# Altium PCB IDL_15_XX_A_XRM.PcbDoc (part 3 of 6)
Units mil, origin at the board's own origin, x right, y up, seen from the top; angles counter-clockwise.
Board outline 6653.34 x 6653.34 mil, 6 copper layers (Top Layer - SIG1, Layer 2 - GND1, Layer 3 - PWR, Layer 4 - PWR, Layer 5 - GND2, Bottom Layer - SIG4), stack 59.843 mil thick; 613 components, 324 nets, 1673 pads, 2316 vias.
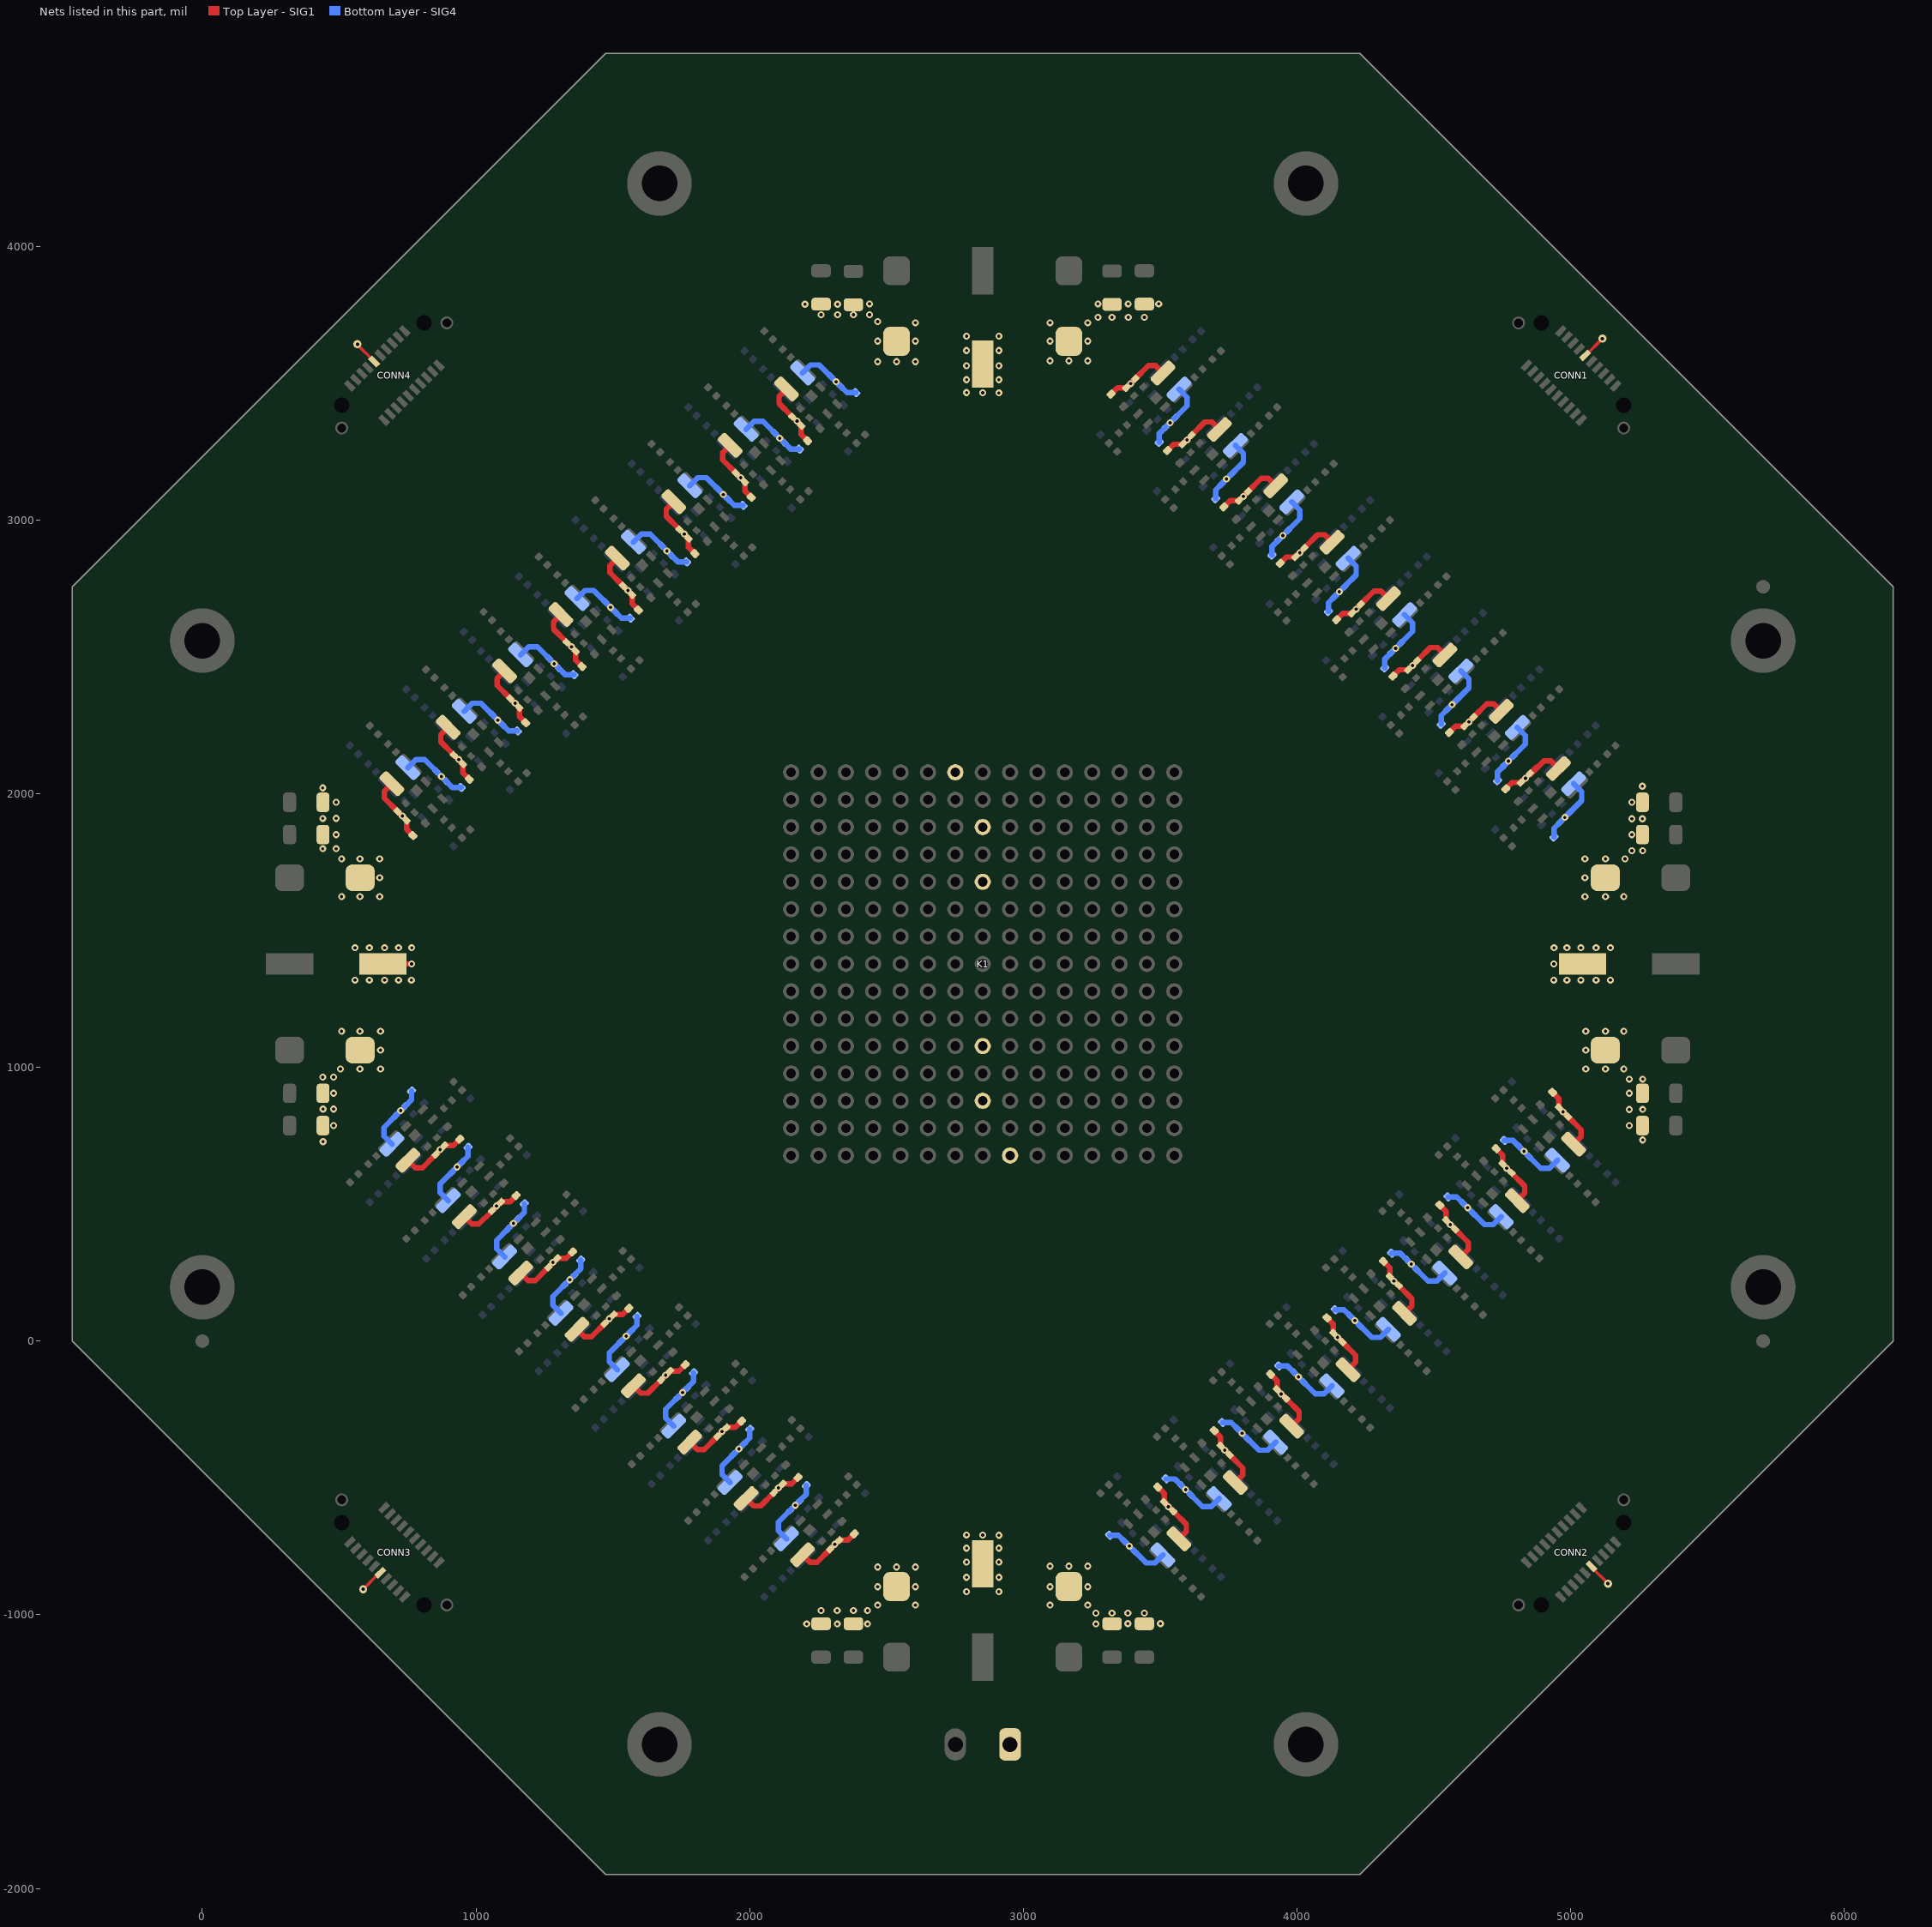
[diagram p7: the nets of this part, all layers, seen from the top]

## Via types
v1: diameter 25.59, hole 11.81, Layer 5 - GND2 to Bottom Layer - SIG4, tented both sides, 1069 vias
v2: diameter 25.59, hole 11.81, Top Layer - SIG1 to Layer 2 - GND1, tented both sides, 851 vias
v3: diameter 25.59, hole 11.81, Top Layer - SIG1 to Bottom Layer - SIG4, tented both sides, 384 vias
v4: diameter 29.53, hole 11.81, Top Layer - SIG1 to Bottom Layer - SIG4, tented both sides, 8 vias
v5: diameter 29.53, hole 11.81, Top Layer - SIG1 to Layer 2 - GND1, tented both sides, 4 vias

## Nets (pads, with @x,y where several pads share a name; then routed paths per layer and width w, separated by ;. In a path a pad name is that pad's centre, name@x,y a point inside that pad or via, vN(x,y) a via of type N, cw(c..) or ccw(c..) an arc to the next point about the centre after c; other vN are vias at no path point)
3V3: A1_C1.1 A1_C2.1 A1_C3.1 A1_L1.2 A2_C1.1 A2_C2.1 A2_C3.1 A2_L1.2 A3_C1.1 A3_C2.1 A3_C3.1 A3_L1.2 A4_C1.1 A4_C2.1 A4_C3.1 A4_L1.2 A5_C1.1 A5_C2.1 A5_C3.1 A5_L1.2 A6_C1.1 A6_C2.1 A6_C3.1 A6_L1.2 A7_C1.1 A7_C2.1 A7_C3.1 A7_L1.2 A8_C1.1 A8_C2.1 A8_C3.1 A8_L1.2 A9_C1.1 A9_C2.1 A9_C3.1 A9_L1.2 A10_C1.1 A10_C2.1 A10_C3.1 A10_L1.2 A11_C1.1 A11_C2.1 A11_C3.1 A11_L1.2 A12_C1.1 A12_C2.1 A12_C3.1 A12_L1.2 A13_C1.1 A13_C2.1 A13_C3.1 A13_L1.2 A14_C1.1 A14_C2.1 A14_C3.1 A14_L1.2 A15_C1.1 A15_C2.1 A15_C3.1 A15_L1.2 A16_C1.1 A16_C2.1 A16_C3.1 A16_L1.2 A17_C1.1 A17_C2.1 A17_C3.1 A17_L1.2 A18_C1.1 A18_C2.1 A18_C3.1 A18_L1.2 A19_C1.1 A19_C2.1 A19_C3.1 A19_L1.2 A20_C1.1 A20_C2.1 A20_C3.1 A20_L1.2 A21_C1.1 A21_C2.1 A21_C3.1 A21_L1.2 A22_C1.1 A22_C2.1 A22_C3.1 A22_L1.2 A23_C1.1 A23_C2.1 A23_C3.1 A23_L1.2 A24_C1.1 A24_C2.1 A24_C3.1 A24_L1.2 A25_C1.1 A25_C2.1 A25_C3.1 A25_L1.2 A26_C1.1 A26_C2.1 A26_C3.1 A26_L1.2 A27_C1.1 A27_C2.1 A27_C3.1 A27_L1.2 A28_C1.1 A28_C2.1 A28_C3.1 A28_L1.2 A29_C1.1 A29_C2.1 A29_C3.1 A29_L1.2 A30_C1.1 A30_C2.1 A30_C3.1 A30_L1.2 A31_C1.1 A31_C2.1 A31_C3.1 A31_L1.2 A32_C1.1 A32_C2.1 A32_C3.1 A32_L1.2 A33_C1.1 A33_C2.1 A33_C3.1 A33_L1.2 A34_C1.1 A34_C2.1 A34_C3.1 A34_L1.2 A35_C1.1 A35_C2.1 A35_C3.1 A35_L1.2 A36_C1.1 A36_C2.1 A36_C3.1 A36_L1.2 A37_C1.1 A37_C2.1 A37_C3.1 A37_L1.2 A38_C1.1 A38_C2.1 A38_C3.1 A38_L1.2 A39_C1.1 A39_C2.1 A39_C3.1 A39_L1.2 A40_C1.1 A40_C2.1 A40_C3.1 A40_L1.2 A41_C1.1 A41_C2.1 A41_C3.1 A41_L1.2 A42_C1.1 A42_C2.1 A42_C3.1 A42_L1.2 A43_C1.1 A43_C2.1 A43_C3.1 A43_L1.2 A44_C1.1 A44_C2.1 A44_C3.1 A44_L1.2 A45_C1.1 A45_C2.1 A45_C3.1 A45_L1.2 A46_C1.1 A46_C2.1 A46_C3.1 A46_L1.2 A47_C1.1 A47_C2.1 A47_C3.1 A47_L1.2 A48_C1.1 A48_C2.1 A48_C3.1 A48_L1.2 A49_C1.1 A49_C2.1 A49_C3.1 A49_L1.2 A50_C1.1 A50_C2.1 A50_C3.1 A50_L1.2 A51_C1.1 A51_C2.1 A51_C3.1 A51_L1.2 A52_C1.1 A52_C2.1 A52_C3.1 A52_L1.2 A53_C1.1 A53_C2.1 A53_C3.1 A53_L1.2 A54_C1.1 A54_C2.1 A54_C3.1 A54_L1.2 A55_C1.1 A55_C2.1 A55_C3.1 A55_L1.2 A56_C1.1 A56_C2.1 A56_C3.1 A56_L1.2 A57_C1.1 A57_C2.1 A57_C3.1 A57_L1.2 A58_C1.1 A58_C2.1 A58_C3.1 A58_L1.2 A59_C1.1 A59_C2.1 A59_C3.1 A59_L1.2 A60_C1.1 A60_C2.1 A60_C3.1 A60_L1.2 A61_C1.1 A61_C2.1 A61_C3.1 A61_L1.2 A62_C1.1 A62_C2.1 A62_C3.1 A62_L1.2 A63_C1.1 A63_C2.1 A63_C3.1 A63_L1.2 A64_C1.1 A64_C2.1 A64_C3.1 A64_L1.2 C4.1 C5.1 C6.1 C7.1 C8.1 C9.1 C10.1 C11.1 C12.1 C14.1 C15.1 C16.1 C17.1 C18.1 C19.1 C20.1 C21.1 C22.1 C23.1 C24.1 C25.1 C26.1 C27.1 C28.1 C29.1 C30.1 C31.1 C32.1 K2.1 | length 17087.9
  Top Layer - SIG1 w20: C32.1@659.5,1377.95 v3(764.82,1377.95) ; 691.01,1957.49 A5_C1.1@713.06,1935.44 ; A5_L1.2@692.59,2036.63 665.16,2009.2 665.16,1983.34 A5_C1.1@713.06,1935.44 ; A4_L1.2@751.12,660.84 778.55,633.41 804.41,633.41 A4_C1.1@852.31,681.3 ; A5_C3.1@769.41,1847.03 746.46,1869.98 A5_C2.1@746.46,1902.03 A5_C1.1@713.06,1935.44 ; 830.26,659.26 A4_C1.1@852.31,681.3 ; 897.02,2163.5 A6_C1.1@919.06,2141.45 ; A6_L1.2@898.6,2242.64 871.17,2215.21 871.17,2189.34 A6_C1.1@919.06,2141.45 ; A4_C3.1@940.72,737.66 917.77,714.71 A4_C2.1@885.72,714.71 A4_C1.1@852.31,681.3 ; A3_L1.2@957.12,454.84 984.56,427.4 1010.42,427.4 A3_C1.1@1058.32,475.3 ; A6_C3.1@975.42,2053.04 952.47,2075.99 A6_C2.1@952.47,2108.04 A6_C1.1@919.06,2141.45 ; 1036.27,453.25 A3_C1.1@1058.32,475.3 ; 1103.02,2369.5 A7_C1.1@1125.07,2347.45 ; A7_L1.2@1104.61,2448.65 1077.17,2421.21 1077.17,2395.35 A7_C1.1@1125.07,2347.45 ; A3_C3.1@1146.72,531.65 1123.77,508.7 A3_C2.1@1091.73,508.7 A3_C1.1@1058.32,475.3 ; A2_L1.2@1163.13,248.83 1190.57,221.39 1216.43,221.39 A2_C1.1@1264.33,269.29 ; A7_C3.1@1181.43,2259.05 1158.48,2282 A7_C2.1@1158.48,2314.05 A7_C1.1@1125.07,2347.45 ; 1242.28,247.24 A2_C2.1@1297.73,302.7 1329.78,302.7 A2_C3.1@1352.73,325.65 ; 1309.03,2575.51 A8_C1.1@1331.08,2553.46 ; A8_L1.2@1310.62,2654.66 1283.18,2627.22 1283.18,2601.36 A8_C1.1@1331.08,2553.46 ; A1_L1.2@1368.78,43.18 1396.22,15.74 1422.08,15.74 A1_C1.1@1469.98,63.64 ; A8_C3.1@1387.44,2465.06 1364.49,2488.01 A8_C2.1@1364.49,2520.06 A8_C1.1@1331.08,2553.46 ; 1447.93,41.59 A1_C2.1@1503.38,97.05 1535.43,97.04 A1_C3.1@1558.38,120 ; 1515.07,2781.55 A25_C1.1@1537.12,2759.5 ; A25_L1.2@1516.66,2860.7 1489.22,2833.26 1489.22,2807.4 A25_C1.1@1537.12,2759.5 ; A64_L1.2@1574.82,-162.86 1602.26,-190.3 1628.12,-190.3 A64_C1.1@1676.02,-142.4 ; A25_C3.1@1593.48,2671.1 1570.53,2694.05 A25_C2.1@1570.53,2726.1 A25_C1.1@1537.12,2759.5 ; 1653.97,-164.45 A64_C2.1@1709.42,-109 1741.47,-109 A64_C3.1@1764.42,-86.05 ; 1721.08,2987.56 A26_C1.1@1743.13,2965.51 ; A26_L1.2@1722.67,3066.7 1695.23,3039.27 1695.23,3013.41 A26_C1.1@1743.13,2965.51 ; A63_L1.2@1780.86,-368.9 1808.3,-396.34 1834.16,-396.34 A63_C1.1@1882.06,-348.44 ; A26_C3.1@1799.48,2877.11 1776.53,2900.06 A26_C2.1@1776.53,2932.1 A26_C1.1@1743.13,2965.51 ; 1860.01,-370.49 A63_C2.1@1915.47,-315.04 1947.51,-315.04 A63_C3.1@1970.46,-292.09 ; 1927.09,3193.57 A27_C1.1@1949.13,3171.52 ; A27_L1.2@1928.67,3272.71 1901.24,3245.28 1901.24,3219.41 A27_C1.1@1949.13,3171.52 ; A62_L1.2@1986.87,-574.91 2014.31,-602.35 2040.17,-602.35 A62_C1.1@2088.07,-554.45 ; A27_C3.1@2005.49,3083.11 1982.54,3106.06 A27_C2.1@1982.54,3138.11 A27_C1.1@1949.13,3171.52 ; 2066.02,-576.5 A62_C2.1@2121.47,-521.04 2153.52,-521.04 A62_C3.1@2176.47,-498.09 ; 2133.09,3399.57 A28_C1.1@2155.14,3377.53 ; A28_L1.2@2134.68,3478.72 2107.25,3451.28 2107.25,3425.42 A28_C1.1@2155.14,3377.53 ; A61_L1.2@2192.88,-780.92 2220.31,-808.35 2246.18,-808.35 A61_C1.1@2294.07,-760.46 ; A28_C3.1@2211.5,3289.12 2188.55,3312.07 A28_C2.1@2188.55,3344.12 A28_C1.1@2155.14,3377.53 ; 2272.03,-782.51 A61_C2.1@2327.48,-727.05 2359.53,-727.05 A61_C3.1@2382.48,-704.1 ; A29_C3.1@3320.52,3459.77 3343.47,3482.72 A29_C2.1@3375.51,3482.72 A29_C1.1@3408.92,3516.13 ; 3430.97,3538.18 A29_C1.1@3408.92,3516.13 ; A60_C3.1@3491.33,-533.25 3514.28,-556.2 A60_C2.1@3514.28,-588.25 3569.74,-643.7 ; A29_L1.2@3510.12,3536.59 3482.68,3564.03 3456.82,3564.03 A29_C1.1@3408.92,3516.13 ; A30_C3.1@3526.52,3253.77 3549.47,3276.72 A30_C2.1@3581.52,3276.72 A30_C1.1@3614.93,3310.12 ; A60_C1.1@3547.69,-621.65 3595.59,-669.55 3595.59,-695.41 A60_L1.2@3568.15,-722.85 ; 3636.98,3332.17 A30_C1.1@3614.93,3310.12 ; A59_C3.1@3697.34,-327.24 3720.29,-350.19 A59_C2.1@3720.29,-382.24 3775.75,-437.69 ; A30_L1.2@3716.12,3330.59 3688.69,3358.02 3662.82,3358.02 A30_C1.1@3614.93,3310.12 ; A31_C3.1@3732.53,3047.76 3755.48,3070.71 A31_C2.1@3787.53,3070.71 A31_C1.1@3820.94,3104.12 ; A59_C1.1@3753.7,-415.65 3801.59,-463.54 3801.59,-489.4 A59_L1.2@3774.16,-516.84 ; 3842.98,3126.17 A31_C1.1@3820.94,3104.12 ; A58_C3.1@3903.35,-121.23 3926.3,-144.18 A58_C2.1@3926.3,-176.23 3981.75,-231.69 ; A31_L1.2@3922.13,3124.58 3894.69,3152.01 3868.83,3152.01 A31_C1.1@3820.94,3104.12 ; A32_C3.1@3938.54,2841.75 3961.49,2864.7 A32_C2.1@3993.54,2864.7 A32_C1.1@4026.94,2898.11 ; A58_C1.1@3959.71,-209.64 4007.6,-257.53 4007.6,-283.4 A58_L1.2@3980.17,-310.83 ; 4048.99,2920.16 A32_C1.1@4026.94,2898.11 ; A57_C3.1@4109.39,84.81 4132.34,61.86 A57_C2.1@4132.34,29.81 A57_C1.1@4165.75,-3.6 ; A32_L1.2@4128.14,2918.57 4100.7,2946.01 4074.84,2946.01 A32_C1.1@4026.94,2898.11 ; A41_C3.1@4144.58,2635.71 4167.53,2658.66 A41_C2.1@4199.58,2658.66 A41_C1.1@4232.98,2692.07 ; A57_L1.2@4186.21,-104.79 4213.64,-77.36 4213.64,-51.49 A57_C1.1@4165.75,-3.6 ; 4187.8,-25.65 A57_C1.1@4165.75,-3.6 ; 4255.03,2714.12 A41_C1.1@4232.98,2692.07 ; A48_C3.1@4315.43,290.85 4338.38,267.9 A48_C2.1@4338.38,235.85 A48_C1.1@4371.79,202.44 ; A41_L1.2@4334.18,2712.53 4306.74,2739.96 4280.88,2739.96 A41_C1.1@4232.98,2692.07 ; A42_C3.1@4350.59,2429.7 4373.54,2452.65 A42_C2.1@4405.59,2452.65 A42_C1.1@4438.99,2486.06 ; A48_L1.2@4392.25,101.25 4419.68,128.68 4419.68,154.55 A48_C1.1@4371.79,202.44 ; 4393.84,180.4 A48_C1.1@4371.79,202.44 ; 4461.04,2508.11 A42_C1.1@4438.99,2486.06 ; A47_C3.1@4521.44,496.86 4544.39,473.91 A47_C2.1@4544.39,441.86 4599.84,386.4 ; A42_L1.2@4540.19,2506.52 4512.75,2533.96 4486.89,2533.96 A42_C1.1@4438.99,2486.06 ; A43_C3.1@4556.59,2223.7 4579.54,2246.65 A43_C2.1@4611.59,2246.65 A43_C1.1@4645,2280.05 ; A47_C1.1@4577.8,408.45 4625.69,360.56 4625.69,334.69 A47_L1.2@4598.26,307.26 ; 4667.05,2302.1 A43_C1.1@4645,2280.05 ; A46_C3.1@4727.45,702.86 4750.4,679.91 A46_C2.1@4750.4,647.87 A46_C1.1@4783.8,614.46 ; A43_L1.2@4746.19,2300.51 4718.76,2327.95 4692.9,2327.95 A43_C1.1@4645,2280.05 ; A45_C3.1@4762.6,2017.69 4785.55,2040.64 A45_C2.1@4817.6,2040.64 A45_C1.1@4851.01,2074.05 4873.06,2096.09 ; A46_L1.2@4804.26,513.26 4831.7,540.7 4831.7,566.56 A46_C1.1@4783.8,614.46 ; 4805.85,592.41 A46_C1.1@4783.8,614.46 ; A45_C1.1@4853.79,2071.26 4901.69,2119.16 4927.55,2119.16 A45_L1.2@4954.99,2091.72 ; A44_C3.1@4933.45,908.87 4956.4,885.92 A44_C2.1@4956.4,853.87 A44_C1.1@4989.81,820.47 ; A44_L1.2@5010.27,719.27 5037.71,746.71 5037.71,772.57 A44_C1.1@4989.81,820.47 ; 5011.86,798.42 A44_C1.1@4989.81,820.47
  Bottom Layer - SIG4 w20: A13_L1.2@693.04,718.92 663.23,748.73 663.23,780.36 A13_C1.1@705.46,822.59 v3(724.95,842.07) A13_C2.1@741.65,858.78 764.62,881.74 A13_C3.1@764.62,913.76 ; A12_L1.2@750.67,2094.71 780.48,2124.52 812.11,2124.52 A12_C1.1@854.34,2082.29 v3(873.83,2062.8) A12_C2.1@890.53,2046.1 913.5,2023.13 A12_C3.1@945.51,2023.13 ; A14_L1.2@899.05,512.91 869.24,542.72 869.24,574.35 A14_C1.1@911.47,616.58 v3(930.96,636.07) A14_C2.1@947.66,652.77 970.63,675.74 A14_C3.1@970.63,707.75 ; A11_L1.2@956.67,2300.71 986.49,2330.53 1018.11,2330.53 A11_C1.1@1060.35,2288.3 v3(1079.83,2268.81) A11_C2.1@1096.54,2252.11 1119.5,2229.14 A11_C3.1@1151.52,2229.14 ; 1103.47,396.57 A15_C1.1@1117.48,410.57 ; A15_L1.2@1105.06,306.9 1075.24,336.72 1075.24,368.34 A15_C1.1@1117.48,410.57 ; A10_L1.2@1162.68,2506.72 1192.5,2536.54 1224.12,2536.54 A10_C1.1@1266.35,2494.3 v3(1285.84,2474.82) A10_C2.1@1302.54,2458.11 1325.51,2435.15 A10_C3.1@1357.53,2435.15 ; A15_C3.1@1176.63,501.74 1176.63,469.73 A15_C2.1@1153.67,446.76 v3(1136.96,430.06) A15_C1.1@1117.48,410.57 ; A16_L1.2@1310.71,101.25 1280.9,131.06 1280.9,162.69 A16_C1.1@1323.13,204.92 v3(1342.61,224.41) A16_C2.1@1359.32,241.11 1382.28,264.08 A16_C3.1@1382.28,296.09 ; A9_L1.2@1368.69,2712.73 1398.5,2742.54 1430.13,2742.54 A9_C1.1@1472.36,2700.31 v3(1491.85,2680.83) A9_C2.1@1508.55,2664.12 1531.52,2641.15 A9_C3.1@1563.53,2641.15 ; 1515.16,-15.12 v3(1548.65,18.37) A49_C2.1@1565.36,35.07 1588.32,58.04 A49_C3.1@1588.33,90.05 ; A49_L1.2@1516.75,-104.79 1486.94,-74.98 1486.94,-43.35 A49_C1.1@1529.17,-1.12 ; A24_L1.2@1574.73,2918.77 1604.55,2948.58 1636.17,2948.58 A24_C1.1@1678.4,2906.35 v3(1697.89,2886.87) A24_C2.1@1714.59,2870.16 1737.56,2847.2 A24_C3.1@1769.57,2847.2 ; 1721.21,-221.16 A50_C1.1@1735.21,-207.16 ; A50_L1.2@1722.79,-310.83 1692.98,-281.02 1692.98,-249.39 A50_C1.1@1735.21,-207.16 ; A23_L1.2@1780.74,3124.78 1810.55,3154.59 1842.18,3154.59 A23_C1.1@1884.41,3112.36 v3(1903.9,3092.87) A23_C2.1@1920.6,3076.17 1943.57,3053.2 A23_C3.1@1975.58,3053.2 ; A50_C3.1@1794.37,-115.99 1794.37,-148 A50_C2.1@1771.4,-170.97 v3(1754.7,-187.67) A50_C1.1@1735.21,-207.16 ; 1927.21,-427.17 A51_C1.1@1941.22,-413.17 ; A51_L1.2@1928.8,-516.84 1898.98,-487.03 1898.98,-455.4 A51_C1.1@1941.22,-413.17 ; A22_L1.2@1986.75,3330.78 2016.56,3360.6 2048.19,3360.6 A22_C1.1@2090.42,3318.37 v3(2109.9,3298.88) A22_C2.1@2126.61,3282.18 2149.57,3259.21 A22_C3.1@2181.59,3259.21 ; A51_C3.1@2000.37,-322 2000.37,-354.01 A51_C2.1@1977.41,-376.98 v3(1960.7,-393.68) A51_C1.1@1941.22,-413.17 ; 2133.22,-633.18 A52_C1.1@2147.22,-619.18 ; A52_L1.2@2134.81,-722.85 2104.99,-693.03 2104.99,-661.41 A52_C1.1@2147.22,-619.18 ; A21_L1.2@2192.75,3536.79 2222.57,3566.61 2254.19,3566.61 A21_C1.1@2296.42,3524.38 v3(2315.91,3504.89) A21_C2.1@2332.62,3488.19 2355.58,3465.22 A21_C3.1@2387.6,3465.22 ; A52_C3.1@2206.38,-528 2206.38,-560.02 A52_C2.1@2183.41,-582.99 v3(2166.71,-599.69) A52_C1.1@2147.22,-619.18 ; A53_C3.1@3315.24,-709.35 3347.25,-709.35 A53_C2.1@3370.22,-732.31 v3(3386.92,-749.02) A53_C1.1@3406.41,-768.5 3448.64,-810.73 3480.27,-810.73 A53_L1.2@3510.08,-780.92 ; A20_C3.1@3496.61,3283.68 3496.61,3315.69 A20_C2.1@3519.58,3338.66 v3(3536.28,3355.36) A20_C1.1@3555.77,3374.85 3598,3417.08 3598,3448.71 A20_L1.2@3568.19,3478.52 ; A54_C3.1@3521.24,-503.34 3553.26,-503.34 A54_C2.1@3576.23,-526.3 v3(3592.93,-543.01) A54_C1.1@3612.42,-562.5 3654.65,-604.73 3686.27,-604.73 A54_L1.2@3716.09,-574.91 ; A19_C3.1@3702.62,3077.67 3702.62,3109.68 A19_C2.1@3725.59,3132.65 v3(3742.29,3149.35) A19_C1.1@3761.78,3168.84 ; A55_C3.1@3727.25,-297.33 3759.27,-297.33 A55_C2.1@3782.23,-320.3 v3(3798.94,-337) A55_C1.1@3818.42,-356.49 3860.66,-398.72 3892.28,-398.72 A55_L1.2@3922.1,-368.9 ; A19_L1.2@3774.19,3272.51 3804.01,3242.7 3804.01,3211.07 A19_C1.1@3761.78,3168.84 ; 3775.78,3182.85 A19_C1.1@3761.78,3168.84 ; A18_C3.1@3908.63,2871.66 3908.63,2903.68 A18_C2.1@3931.6,2926.64 v3(3948.3,2943.35) A18_C1.1@3967.79,2962.83 4010.02,3005.07 4010.02,3036.69 A18_L1.2@3980.2,3066.51 ; A56_C3.1@3933.29,-91.29 3965.31,-91.29 A56_C2.1@3988.27,-114.26 v3(4004.98,-130.96) A56_C1.1@4024.46,-150.45 ; 4038.47,-164.45 A56_C1.1@4024.46,-150.45 ; A17_C3.1@4114.64,2665.65 4114.64,2697.67 A17_C2.1@4137.6,2720.64 v3(4154.31,2737.34) A17_C1.1@4173.79,2756.83 4216.02,2799.06 4216.02,2830.68 A17_L1.2@4186.21,2860.5 ; A56_L1.2@4128.14,-162.86 4098.32,-192.68 4066.7,-192.68 A56_C1.1@4024.46,-150.45 ; A33_C3.1@4139.33,114.75 4171.35,114.75 A33_C1.1@4230.51,55.59 4272.74,13.36 4304.36,13.36 A33_L1.2@4334.18,43.18 ; A40_C3.1@4320.68,2459.61 4320.68,2491.63 A40_C2.1@4343.64,2514.6 4422.07,2593.02 4422.07,2624.64 A40_L1.2@4392.25,2654.46 ; A34_C3.1@4345.34,320.76 4377.36,320.76 A34_C2.1@4400.32,297.79 A34_C1.1@4436.51,261.6 4478.74,219.37 4510.37,219.37 A34_L1.2@4540.18,249.19 ; A39_C3.1@4526.68,2253.61 4526.68,2285.62 A39_C1.1@4585.84,2344.78 ; A35_C3.1@4551.35,526.77 4583.36,526.77 A35_C1.1@4642.52,467.61 4684.75,425.38 4716.38,425.38 A35_L1.2@4746.19,455.19 ; A39_L1.2@4598.26,2448.45 4628.07,2418.63 4628.07,2387.01 A39_C1.1@4585.84,2344.78 ; 4599.84,2358.78 A39_C1.1@4585.84,2344.78 ; A38_C3.1@4732.69,2047.6 4732.69,2079.61 A38_C1.1@4791.85,2138.77 4834.08,2181 4834.08,2212.63 A38_L1.2@4804.27,2242.44 ; A36_C3.1@4757.36,732.77 4789.37,732.77 A36_C1.1@4848.53,673.62 ; 4862.53,659.61 A36_C1.1@4848.53,673.62 ; A37_C3.1@4938.7,1841.59 4938.7,1873.61 5011.86,1946.77 ; A36_L1.2@4952.2,661.2 4922.38,631.39 4890.76,631.39 A36_C1.1@4848.53,673.62 ; A37_C1.1@4997.86,1932.76 5040.09,1974.99 5040.09,2006.62 A37_L1.2@5010.27,2036.44
  other v3: 2208.39,-1033.46 2319.94,-1033.46 2430.48,-1033.46 3264.82,-1033.46 3381.93,-1032.48 3500.53,-1032.48 3264.82,-994.09 3323.87,-994.09 3381.93,-994.09 3442.24,-994.09 2260.88,-984.25 2319.61,-984.25 2378.99,-984.25 2430.48,-984.25 2467.57,-964.57 2605.37,-964.57 3097.5,-964.57 3235.29,-964.57 2792.38,-915.35 2910.49,-915.35 2467.57,-897.7 2605.37,-897.7 3097.5,-897.7 3235.29,-897.7 2792.38,-863.24 2910.49,-863.24 2467.57,-825.32 2536.47,-825.32 2605.37,-825.32 3097.5,-822.18 3166.39,-822.18 3235.29,-822.18 2792.38,-807.09 2910.49,-807.09 2792.38,-756.48 2910.49,-756.48 2310.78,-742.36 2910.49,-709.35 2792.38,-708.26 2851.43,-708.66 3529.6,-604.95 2104.77,-536.36 3735.6,-398.94 1898.76,-330.35 3941.61,-192.93 1692.72,-124.31 4147.65,13.11 4211.02,75.08 1486.68,81.73 4353.69,219.15 4417.03,281.09 1281.03,287.38 4559.7,425.15 4623.03,487.1 1075.02,493.39 4765.71,631.16 4829.04,693.1 869.01,699.4 441,728.86 5262.85,734.9 479.39,787.15 5213.64,787.4 4971.72,837.17 5213.64,846.13 5262.85,846.46 441,847.45 479.39,847.45 479.39,905.51 5213.64,905.51 5213.64,957 5262.85,957 440.02,964.57 479.39,964.57 505.07,994.09 575.78,994.09 651.3,994.09 5054.71,994.09 5127.09,994.09 5193.95,994.09 651.3,1062.99 5054.71,1062.99 508.91,1131.89 575.78,1131.89 651.3,1131.89 5054.71,1131.89 5127.09,1131.89 5193.95,1131.89 558.13,1318.9 610.24,1318.9 666.39,1318.9 717,1318.9 764.14,1318.9 4937.65,1318.9 4985.86,1318.9 5036.47,1318.9 5092.63,1318.9 5144.74,1318.9 4938.05,1377.95 558.13,1437.01 610.24,1437.01 666.39,1437.01 717,1437.01 765.22,1437.01 4938.73,1437.01 4985.86,1437.01 5036.47,1437.01 5092.63,1437.01 5144.74,1437.01 508.91,1624.02 575.78,1624.02 648.16,1624.02 5051.56,1624.02 5127.09,1624.02 5193.95,1624.02 648.16,1692.91 5051.56,1692.91 508.91,1761.81 575.78,1761.81 648.16,1761.81 5051.56,1761.81 5127.09,1761.81 5197.8,1761.81 5223.48,1791.34 5262.85,1791.34 440.02,1798.9 489.23,1798.9 489.23,1850.39 5223.48,1850.39 5223.48,1908.45 5261.87,1908.45 440.02,1909.45 489.23,1909.77 4978.37,1913.28 731.15,1918.74 489.23,1968.5 5223.48,1968.76 440.02,2021 5261.87,2027.05 4834.3,2055.95 4772.36,2119.28 937.16,2124.74 4628.3,2261.96 4566.35,2325.29 1143.17,2330.75 4422.29,2467.97 4360.35,2531.3 1349.17,2536.76 4216.28,2673.97 1555.22,2742.8 4010.24,2880.01 1761.22,2948.81 3804.23,3086.02 1967.23,3154.81 3598.22,3292.03 2173.24,3360.82 2851.43,3464.57 2910.49,3464.17 2792.38,3465.25 3392.22,3498.04 2792.38,3512.38 2910.49,3512.38 2792.38,3562.99 2910.49,3562.99 2467.57,3578.08 2536.47,3578.08 2605.37,3578.08 3097.5,3581.23 3166.39,3581.23 3235.29,3581.23 2792.38,3619.15 2910.49,3619.15 2467.57,3653.61 2605.37,3653.61 3097.5,3653.61 3235.29,3653.61 2792.38,3671.26 2910.49,3671.26 2605.37,3720.47 3097.5,3720.47 3235.29,3720.47 2467.57,3724.32 3272.38,3740.16 3323.87,3740.16 3383.25,3740.16 3441.98,3740.16 2260.63,3750 2320.93,3750 2378.99,3750 2438.05,3750 2202.34,3788.39 2320.93,3788.39 2438.05,3789.37 3272.38,3789.37 3382.93,3789.37 3494.48,3789.37
BIAS-DB: CONN1.11 CONN2.11 CONN3.11 CONN4.11 K1.A1 K1.A2 K1.B3 K1.B13 K1.B14 K1.C3 K1.C11 K1.C12 K1.N4 K1.N5 K1.N13 K1.P2 K1.P3 K1.P13 K1.R14 K1.R15 | length 752.5
  Top Layer - SIG1 w11: CONN3.11@753.03,-698.27 v3(871.12,-580.19) ; CONN4.11@775.21,3476.45 v3(926.24,3325.42) ; v3(4804.19,3311.02) 4806.97,3311.02 CONN1.11@4949.93,3453.99 ; v3(4809.58,-602.46) CONN2.11@4927.66,-720.55
BIAS-DB: CONN1.10 CONN2.10 CONN3.10 CONN4.10 K1.G1 K1.H3 K1.H5 K1.H11 K1.H13 K1.J15 | length 350
  Top Layer - SIG1 w11: v4@566.99,3640.13 CONN4.10@627.66,3579.45 ; v4@589.35,-906.5 v4(587.65,-906.5) 648.33,-845.82 CONN3.10@650.03,-845.82 ; CONN1.10@5052.94,3601.53 5054.64,3601.53 v4(5115.31,3662.21) ; CONN2.10@5075.21,-823.55 5075.21,-825.25 v4(5135.89,-885.93)
  other v4: 566.99,3641.83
